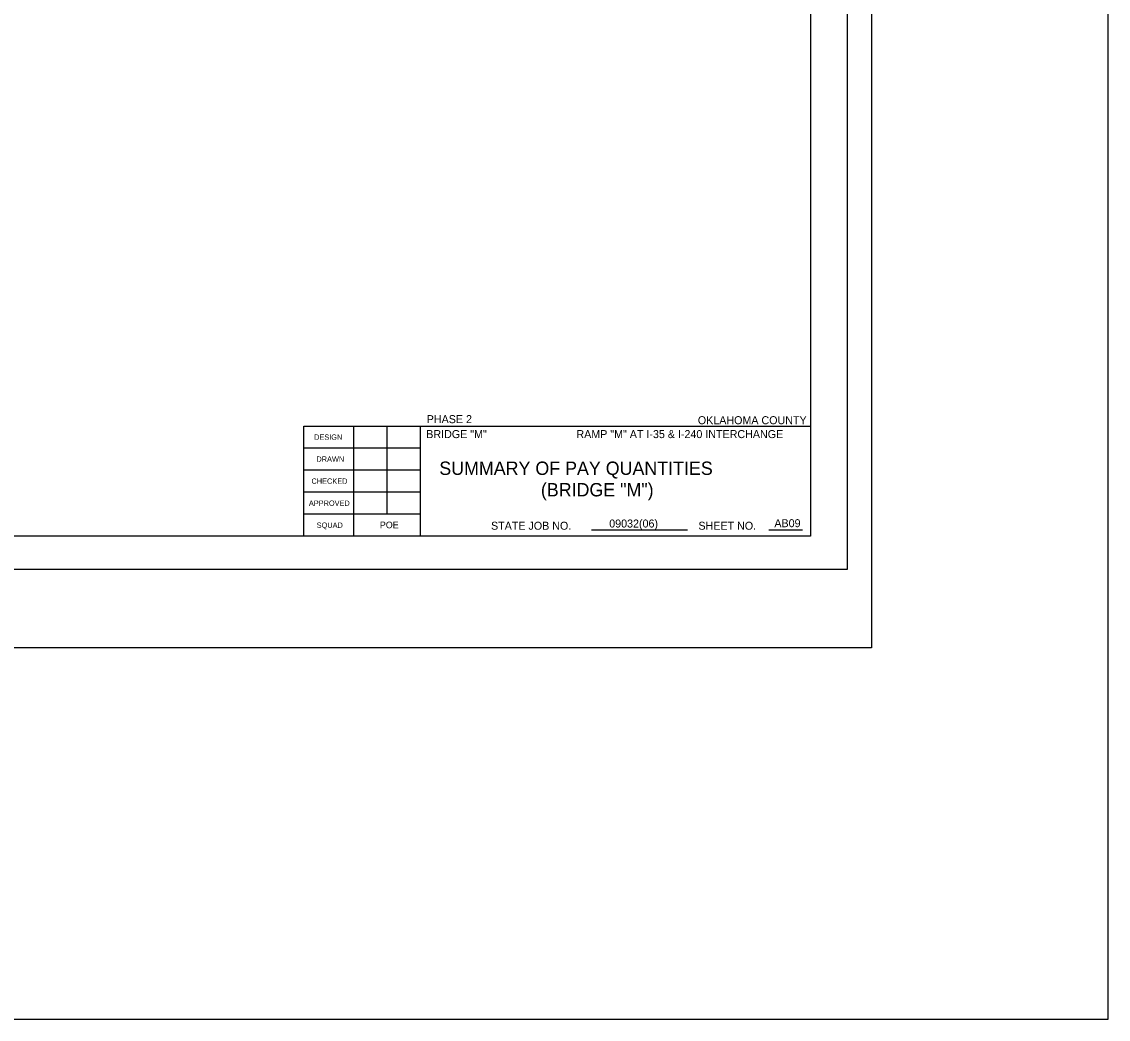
# Model space of a CAD drawing. Extents: x 12303.1 to 12355.9, y 579 to 640.5.
# Drawn here: x 12339.62 to 12355.91, y 579.03 to 593.99 of the extents above; entities that cross this region are included whole.
import ezdxf

# ---------------------------------------------------------------- set-up
doc = ezdxf.new("R2010")
doc.units = 0
for name, color, linetype in [('S', 7, 'Continuous'), ('SHT_Plot_Shape_Full', 7, 'Continuous'), ('SHT_Plot_Shape_Half', 7, 'Continuous'), ('SHT_Sheet_Border', 7, 'Continuous'), ('SHT_Standard_Sheet_Lines', 7, 'Continuous'), ('SHT_Standard_Sheet_Txt', 7, 'Continuous'), ('T', 7, 'Continuous'), ('T-Title', 7, 'Continuous')]:
    doc.layers.add(name, color=color, linetype=linetype)

msp = doc.modelspace()

# ---------------------------------------------------------------- linework, layer by layer
at = {"layer": 'S'}
msp.add_lwpolyline([(12355.912, 640.488), (12312.476, 640.488), (12312.476, 579.031), (12355.912, 579.031)], close=True, dxfattribs=at)
at = {"layer": 'SHT_Plot_Shape_Full'}
msp.add_lwpolyline([(12316.36, 608.6), (12352.36, 608.6), (12352.36, 584.6), (12316.36, 584.6)], close=True, dxfattribs=at)
at = {"layer": 'SHT_Plot_Shape_Half'}
msp.add_lwpolyline([(12317.998, 607.775), (12351.998, 607.775), (12351.998, 585.775), (12317.998, 585.775)], close=True, dxfattribs=at)
at = {"layer": 'SHT_Sheet_Border'}
for p, q in [((12343.848, 586.275), (12343.848, 587.925)), ((12343.848, 587.925), (12351.448, 587.925)), ((12345.598, 586.275), (12345.598, 587.926))]:
    msp.add_line(p, q, dxfattribs=at)
msp.add_lwpolyline([(12351.448, 586.275), (12319.948, 586.275), (12319.948, 607.275), (12351.448, 607.275)], close=True, dxfattribs=at)
at = {"layer": 'SHT_Standard_Sheet_Lines'}
for p, q in [((12344.598, 586.275), (12344.598, 587.926)), ((12345.098, 586.605), (12345.098, 587.926)), ((12348.159, 586.371), (12349.599, 586.371)), ((12350.823, 586.371), (12351.326, 586.371))]:
    msp.add_line(p, q, dxfattribs=at)
for points in [[(12345.598, 587.595), (12343.848, 587.595)], [(12345.598, 587.265), (12343.848, 587.265)], [(12345.598, 586.935), (12343.848, 586.935)], [(12345.598, 586.605), (12343.848, 586.605)]]:
    msp.add_lwpolyline(points, dxfattribs=at)

# ---------------------------------------------------------------- texts
at = {"layer": 'SHT_Standard_Sheet_Txt'}
for s, height, p in [('DESIGN', 0.08, (12344, 587.72)), ('DRAWN', 0.08, (12344.035, 587.39)), ('CHECKED', 0.08, (12343.961, 587.06)), ('APPROVED', 0.08, (12343.922, 586.729)), ('SQUAD', 0.08, (12344.039, 586.399)), ('STATE JOB NO.', 0.12, (12346.654, 586.371)), ('SHEET NO. ', 0.12, (12349.765, 586.371))]:
    msp.add_text(s, height=height, dxfattribs=at).set_placement(p)
at = {"layer": 'T'}
for s, height, p in [('PHASE 2', 0.12, (12345.69, 587.969)), ('OKLAHOMA COUNTY', 0.12, (12349.756, 587.953)), ('BRIDGE "M"', 0.12, (12345.683, 587.745)), ('RAMP "M" AT I-35 & I-240 INTERCHANGE', 0.12, (12347.935, 587.745)), ('09032(06)', 0.12, (12348.427, 586.404)), ('AB09', 0.12, (12350.904, 586.409)), ('POE', 0.1, (12344.987, 586.393))]:
    msp.add_text(s, height=height, dxfattribs=at).set_placement(p)
at = {"layer": 'T-Title'}
for s, p in [('SUMMARY OF PAY QUANTITIES', (12345.878, 587.193)), ('(BRIDGE "M")', (12347.402, 586.871))]:
    msp.add_text(s, height=0.2, dxfattribs=at).set_placement(p)

doc.saveas('drawing.dxf')
